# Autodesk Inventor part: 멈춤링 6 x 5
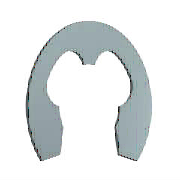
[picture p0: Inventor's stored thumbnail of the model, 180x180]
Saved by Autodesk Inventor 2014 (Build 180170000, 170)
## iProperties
Created: 2012-02
Part Number: 멈춤링 6 x 5
Material: 강철, 연강
Description: 스프링 리테이닝 링
Document SubType Name: Modeling
Standard: JIS B 2805
Designer: mduedu
Standards Organization: JIS
Language: ko-KR
Size Designation: 5
Categories: <MemberInstance><Categories><Category DisplayName="샤프트 부품" InternalName="7f7aeb1f-a693-4053-b835-cee3144e0d98" Mnemonic="SHFT"><Category DisplayName="써클립" Inter
Density: 1 g/cm^3
Appearance: Blue - Wall Paint - Glossy
IsCustomPart: 1
Author: mduedu
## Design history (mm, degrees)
sketch "스케치1"
  geometry: L1 (-0.5, 0.024)-(0, 0.024) reference; L2 (-3.206, 0)-(3.486, 0) reference; L3 (-2.291, -3.976)-(2.291, -3.976); L4 (0, 1.949)-(0, -3.479) reference; L5 (-3, -1.976)-(-2.51, -1.976); L6 (-0.5, 0.024)-(-0.5, 0.509); L7 (0, 2.524)-(2.53, 2.524); L8 (-2.291, -3.976)-(-3.051, -6.131); L9 (0, -0.476)-(-1.278, -0.476); L10 (2.291, -3.976)-(3.051, -6.131); L11 (3, -1.976)-(2.51, -1.976); L12 (0.5, 0.024)-(0.5, 0.509); C1 r 3 at (0, -2.976); A1 r 2.5 centre (0, -2.976) between (-2.368, -2.174) and (-2.291, -3.976); A2 r 0.5 centre (0, 0.024) between (-0.5, 0.024) and (0.5, 0.024); A3 r 5.5 centre (0, -2.976) between (4.351, -6.34) and (-4.351, -6.34); A4 r 4 centre (0, -2.976) between (-1, 0.897) and (-3.529, -1.094); A5 r 0.4 centre (-0.9, 0.509) between (-0.5, 0.509) and (-1, 0.897); A6 r 0.6 centre (-3, -1.376) between (-3.529, -1.094) and (-3, -1.976); A7 r 0.15 centre (-2.51, -2.126) between (-2.368, -2.174) and (-2.51, -1.976); A8 r 0.75 centre (-3.758, -5.881) between (-4.351, -6.34) and (-3.051, -6.131); A9 r 0.75 centre (3.758, -5.881) between (3.051, -6.131) and (4.351, -6.34); A10 r 2.5 centre (0, -2.976) between (2.291, -3.976) and (2.368, -2.174); A11 r 0.15 centre (2.51, -2.126) between (2.51, -1.976) and (2.368, -2.174); A12 r 0.6 centre (3, -1.376) between (3, -1.976) and (3.529, -1.094); A13 r 4 centre (0, -2.976) between (3.529, -1.094) and (1, 0.897); A14 r 0.4 centre (0.9, 0.509) between (1, 0.897) and (0.5, 0.509); 1 further point
  constraints: 30 point on circle, 20 end point, 15 centre point, 13 symmetric about line, 12 tangent, 8 point on line, 4 parallel, 2 coincident, 2 horizontal, 1 concentric, 1 perpendicular, 1 vertical alignment, 9 other
  dimensions: "d0" = 6 diameter of C1 (= WD); "d3" = 1 distance from line of A1.centre L3 (= 0.2 x ND); "d4" = 0.5 radius of A2 (= 0.1 x ND); "d5" = 11 diameter of A3 (= SD2); "d8" = 4 radius of A4 (= 0.8 x ND); "d9" = 1 distance from line of A1.centre L5 (= 0.2 x ND); "d10" = 0.4 radius of A5 (= 0.08 x ND); "d11" = 0.6 radius of A6 (= 0.12 x ND); "d12" = 0.15 radius of A7 (= 0.03 x ND); "d13" = 0.75 radius of A8 (= 0.15 x ND); "d14" = 2.5 distance from line of A1.centre L9 (= 0.5 x ND); "d15" = 2.5 radius of A1 (= 0.5 x ND)
extrude "본체" new body sketch "스케치1" distance "d16" = 0.6 (= SD); taper "d17" = 0 deg
workaxis "Work Axis1"
workaxis "Work Axis2"
workplane "Work Plane1"
body "Solid1"
other parameters: "ND" = 5 [user parameter; used in 14 equation terms], "SD" = 0.6 [user parameter; used in 1 equation term], "WD" = 6 (= WDMIN) [user parameter; used in 1 equation term], "d1" = 8 (= 1.6 x ND), "d2" = 5 (= ND), "SD2" = 11 [user parameter; used in 1 equation term], "d6" = 5 (= ND), "d7" = 0.75 (= 0.15 x ND), "d18" = 0, "d19" = 0, "d27" = 0, "d28" = 0, "WDMIN" = 6 [user parameter; used in 1 equation term], "SNB" = 0.7 [user parameter], "WDMAX" = 8 [user parameter], "BUBRMI" = 1.2 [user parameter]
